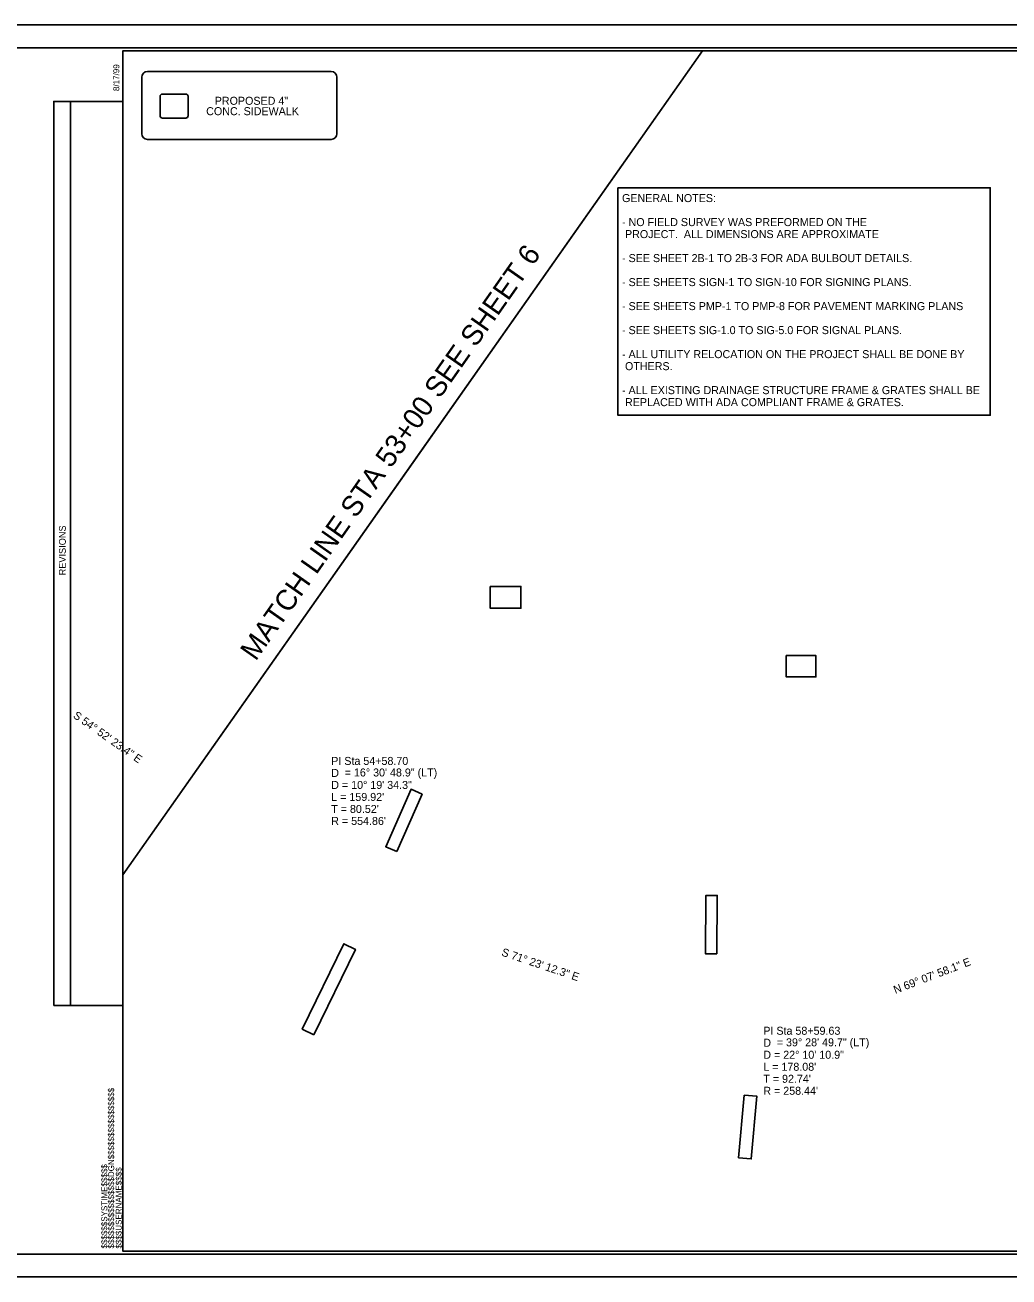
# Model space of a CAD drawing. Extents: x 928111 to 937215, y 684185 to 686530.
# Drawn here: x 931634 to 932495, y 684185 to 685280 of the extents above; entities that cross this region are included whole.
import ezdxf

# ---------------------------------------------------------------- set-up
doc = ezdxf.new("R2010")
doc.units = 0
for name, color, linetype in [('Exist Horizontal Alignment Curve and Spiral Data', 7, 'Continuous'), ('Exist Horizontal Alignment Direction Label', 7, 'Continuous'), ('Matchline', 7, 'Continuous'), ('Matchline Text', 7, 'Continuous'), ('Old_Level_2', 7, 'Continuous'), ('Prop DSN Text', 7, 'Continuous'), ('Sheet Cutting Line CELL', 7, 'Continuous'), ('Sheet Layout Plan Border', 7, 'Continuous'), ('Sheet Plan CELL', 7, 'Continuous'), ('Sheet Plan Layout CELL', 7, 'Continuous'), ('Sheet Plot Border Outside CELL', 7, 'Continuous')]:
    doc.layers.add(name, color=color, linetype=linetype)

msp = doc.modelspace()

# ---------------------------------------------------------------- linework, layer by layer
at = {"layer": 'Matchline'}
msp.add_line((931719.8, 684536.9), (932226.8, 685257.7), dxfattribs=at)
at = {"layer": 'Old_Level_2'}
for p, q in [((931774.7, 685219.8), (931754.3, 685219.8)), ((931752.3, 685217.8), (931752.3, 685200.8)), ((931776.7, 685200.8), (931776.7, 685217.8)), ((931754.3, 685198.8), (931774.7, 685198.8))]:
    msp.add_line(p, q, dxfattribs=at)
for centre, start, end in [((931754.3, 685217.8), 90, 180), ((931774.7, 685217.8), 0, 90), ((931754.3, 685200.8), 180, 270), ((931774.7, 685200.8), 270, 0)]:
    msp.add_arc(centre, 2, start, end, dxfattribs=at)
at = {"layer": 'Prop DSN Text'}
for p, q in [((931736.3, 685234.5), (931736.3, 685185.1)), ((931736.3, 685185.1), (931736.3, 685234.5)), ((931901.9, 685239.5), (931741.3, 685239.5)), ((931741.3, 685239.5), (931901.9, 685239.5)), ((931906.9, 685185.1), (931906.9, 685234.5)), ((931906.9, 685234.5), (931906.9, 685185.1)), ((931741.3, 685180.1), (931901.9, 685180.1)), ((931901.9, 685180.1), (931741.3, 685180.1))]:
    msp.add_line(p, q, dxfattribs=at)
for points in [[(932152.8, 685137.8), (932478.5, 685137.8), (932478.5, 684938.8), (932152.8, 684938.8)], [(932041.1, 684789.2), (932068, 684789.2), (932068, 684770.1), (932041.1, 684770.1)], [(932300, 684728.7), (932326, 684728.7), (932326, 684710), (932300, 684710)], [(931959.5, 684557.2), (931981.5, 684607.4), (931971.8, 684611.7), (931949.7, 684561.5)], [(932239.3, 684467.8), (932239.7, 684518.8), (932229.8, 684518.9), (932229.4, 684467.9)], [(931886.8, 684396.9), (931923.2, 684471.7), (931913.1, 684476.6), (931876.7, 684401.9)], [(932263.2, 684344.2), (932258.3, 684289.4), (932269.4, 684288.4), (932274.4, 684343.2)]]:
    msp.add_lwpolyline(points, close=True, dxfattribs=at)
for centre, start, end in [((931741.3, 685234.5), 90, 180), ((931741.3, 685234.5), 90, 180), ((931901.9, 685234.5), 360, 90), ((931901.9, 685234.5), 360, 90), ((931741.3, 685185.1), 180, 270), ((931741.3, 685185.1), 180, 270), ((931901.9, 685185.1), 270, 360), ((931901.9, 685185.1), 270, 360)]:
    msp.add_arc(centre, 5, start, end, dxfattribs=at)
at = {"layer": 'Sheet Cutting Line CELL'}
for p, q in [((933236.8, 685280.2), (931553.3, 685280.2)), ((931553.3, 684185.2), (933236.8, 684185.2))]:
    msp.add_line(p, q, dxfattribs=at)
at = {"layer": 'Sheet Layout Plan Border'}
for p, q in [((931973.3, 684897.3), (932226.8, 685257.7)), ((931719.8, 684536.9), (931973.3, 684897.3))]:
    msp.add_line(p, q, dxfattribs=at)
at = {"layer": 'Sheet Plan CELL'}
for p, q in [((931719.8, 685257.7), (931719.8, 685257.7)), ((931673.8, 684422.7), (931673.8, 685213.3)), ((931719.8, 684207.7), (931719.8, 684207.7))]:
    msp.add_line(p, q, dxfattribs=at)
for points in [[(931566.3, 684205.2), (933232.3, 684205.2), (933232.3, 685260.2), (931566.3, 685260.2)], [(933219.8, 685257.7), (931719.8, 685257.7), (931719.8, 684207.7), (933219.8, 684207.7)], [(931719.8, 684207.7), (931719.8, 685257.6), (933019.7, 685257.7), (933019.8, 685107.6), (933219.8, 685107.6), (933219.8, 684207.7)], [(931659.3, 684422.6), (931659.3, 685213.3), (931719.8, 685213.3), (931719.8, 684422.7)]]:
    msp.add_lwpolyline(points, close=True, dxfattribs=at)
at = {"layer": 'Sheet Plan Layout CELL'}
msp.add_lwpolyline([(931719.8, 685257.6), (931719.8, 684207.7), (933219.8, 684207.7), (933219.8, 685046.2), (932980.5, 685046.2), (932980.5, 685257.7)], close=True, dxfattribs=at)
at = {"layer": 'Sheet Plot Border Outside CELL'}
msp.add_lwpolyline([(931553.3, 684185.2), (933236.8, 684185.2), (933236.8, 685280.2), (931553.3, 685280.2)], close=True, dxfattribs=at)

# ---------------------------------------------------------------- texts
at = {"layer": 'Exist Horizontal Alignment Curve and Spiral Data'}
for s, p in [('PI Sta 54+58.70', (931902, 684633)), ('D', (931902, 684622.5)), ('= 16%%d 30\' 48.9" (LT)', (931913.8, 684622.9)), ('D = 10%%d 19\' 34.3"', (931902, 684612)), ("L = 159.92'", (931902, 684601.5)), ("T = 80.52'", (931902, 684591)), ("R = 554.86'", (931902, 684580.5)), ('PI Sta 58+59.63', (932280, 684397)), ('D', (932280, 684386.5)), ('= 39%%d 28\' 49.7" (LT)', (932291.8, 684386.9)), ('D = 22%%d 10\' 10.9"', (932280, 684376)), ("L = 178.08'", (932280, 684365.5)), ("T = 92.74'", (932280, 684355)), ("R = 258.44'", (932280, 684344.5))]:
    msp.add_text(s, height=7, dxfattribs=at).set_placement(p)
at = {"layer": 'Exist Horizontal Alignment Direction Label'}
for s, rotation, p in [('S 54%%d 52\' 23.4" E', 324.8732, (931675.6, 684674.8)), ('S 71%%d 23\' 12.3" E', 341.3867, (932050.4, 684466.4)), ('N 69%%d 07\' 58.1" E', 20.8672, (932395.5, 684432.7))]:
    msp.add_text(s, height=7, rotation=rotation, dxfattribs=at).set_placement(p)
at = {"layer": 'Matchline Text'}
msp.add_text('MATCH LINE STA 53+00 SEE SHEET 6 ', height=18, rotation=54.9555, dxfattribs=at).set_placement((931835.9, 684723.2))
at = {"layer": 'Prop DSN Text'}
for s, p in [('CONC. SIDEWALK', (931792.6, 685201.3)), ('PROPOSED 4"', (931800.1, 685210.4)), ('GENERAL NOTES:', (932156.4, 685125.3)), ('- NO FIELD SURVEY WAS PREFORMED ON THE ', (932156.4, 685104.3)), (' PROJECT.  ALL DIMENSIONS ARE APPROXIMATE', (932156.4, 685093.8)), ('- SEE SHEET 2B-1 TO 2B-3 FOR ADA BULBOUT DETAILS.', (932156.4, 685072.8)), ('- SEE SHEETS SIGN-1 TO SIGN-10 FOR SIGNING PLANS.', (932156.4, 685051.8)), ('- SEE SHEETS PMP-1 TO PMP-8 FOR PAVEMENT MARKING PLANS  ', (932156.4, 685030.8)), ('- SEE SHEETS SIG-1.0 TO SIG-5.0 FOR SIGNAL PLANS.', (932156.4, 685009.8)), ('- ALL UTILITY RELOCATION ON THE PROJECT SHALL BE DONE BY ', (932156.4, 684988.8)), (' OTHERS.', (932156.4, 684978.3)), ('- ALL EXISTING DRAINAGE STRUCTURE FRAME & GRATES SHALL BE ', (932156.4, 684957.3)), (' REPLACED WITH ADA COMPLIANT FRAME & GRATES.', (932156.4, 684946.8))]:
    msp.add_text(s, height=7, rotation=360, dxfattribs=at).set_placement(p)
at = {"layer": 'Sheet Plan CELL'}
for s, height, p in [('8/17/99', 5.25, (931716.6, 685222.4)), ('REVISIONS', 6, (931669.8, 684798.8)), ('$$$$$$$$$$$$$$$$DGN$$$$$$$$$$$$$$$$', 5.25, (931712.1, 684210)), ('$$$$$$SYSTIME$$$$$', 5.25, (931706.1, 684210)), ('$$$$USERNAME$$$$', 5.25, (931718.7, 684210))]:
    msp.add_text(s, height=height, rotation=90, dxfattribs=at).set_placement(p)

doc.saveas('drawing.dxf')
